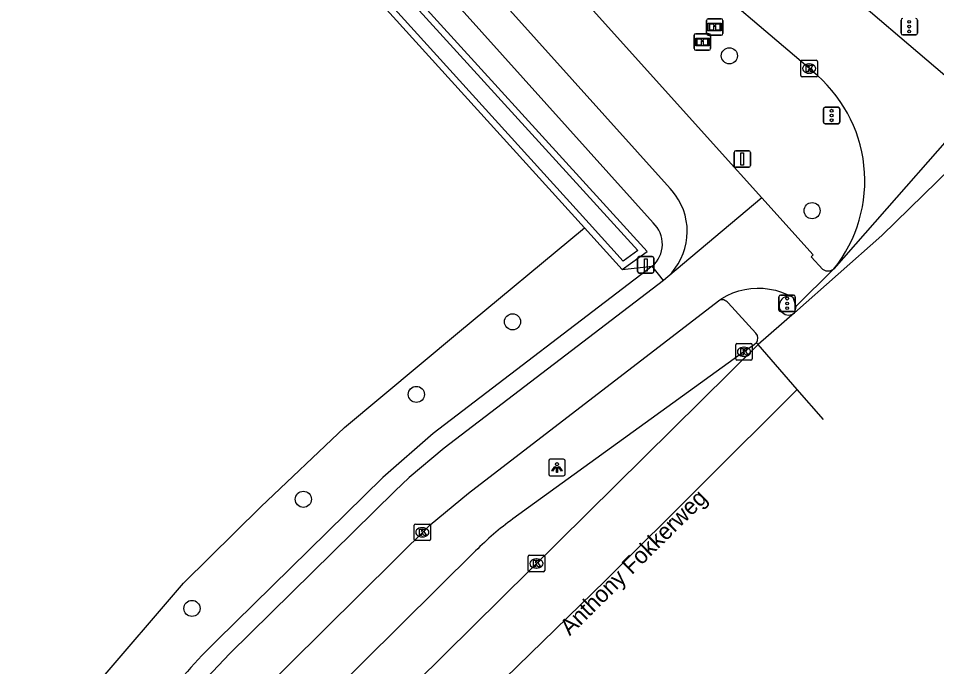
# Model space of a CAD drawing. Extents: x 157321 to 158827, y 386650 to 388532.
# Drawn here: x 158300.1 to 158355.8, y 386849.9 to 386889.2 of the extents above; entities that cross this region are included whole.
import ezdxf

# ---------------------------------------------------------------- set-up
doc = ezdxf.new("R2010")
doc.units = 0
for name, color, linetype in [('IMGEO_Boom', 7, 'Continuous'), ('IMGEO_Bouwland', 7, 'Continuous'), ('IMGEO_Fietspad_gesloten', 7, 'Continuous'), ('IMGEO_Grasland_overig', 7, 'Continuous'), ('IMGEO_Groenvoorziening', 7, 'Continuous'), ('IMGEO_Informatiebord', 7, 'Continuous'), ('IMGEO_Kolk', 7, 'Continuous'), ('IMGEO_Lichtpunt', 7, 'Continuous'), ('IMGEO_Openbare_ruimte_label', 7, 'Continuous'), ('IMGEO_OVBaan_open', 7, 'Continuous'), ('IMGEO_Rijbaan_lokaal_gesloten', 7, 'Continuous'), ('IMGEO_Rijbaan_regionaal_gesloten', 7, 'Continuous'), ('IMGEO_Verkeersbordpaal', 7, 'Continuous'), ('IMGEO_Verkeersregelinstallatiepaal', 7, 'Continuous'), ('IMGEO_Voetpad_open', 7, 'Continuous'), ('IMGEO_Waterloop', 7, 'Continuous')]:
    doc.layers.add(name, color=color, linetype=linetype)

msp = doc.modelspace()

# ---------------------------------------------------------------- linework, layer by layer
at = {"layer": 'IMGEO_Boom'}
for centre in [(158343.218, 386886.885), (158348.234, 386877.495), (158330.072, 386870.76), (158324.239, 386866.357), (158317.388, 386859.998), (158310.633, 386853.383)]:
    msp.add_circle(centre, 0.489, dxfattribs=at)
at = {"layer": 'IMGEO_Bouwland'}
msp.add_lwpolyline([(158334.432, 386876.454), (158305.326, 386908.574)], dxfattribs=at)
at = {"layer": 'IMGEO_Fietspad_gesloten'}
for points in [[(158309.295, 386916.737), (158310.55, 386915.72), (158312.938, 386913.791), (158314.825, 386912.014), (158342.42, 386881.352), (158345.182, 386878.283)], [(158339.487, 386873.493), (158339.722, 386873.737), (158339.934, 386874.001), (158340.121, 386874.282), (158340.282, 386874.58), (158340.417, 386874.89), (158340.523, 386875.211), (158340.599, 386875.541), (158340.646, 386875.876), (158340.663, 386876.214), (158340.65, 386876.552), (158340.607, 386876.887), (158340.534, 386877.217), (158340.431, 386877.54), (158340.3, 386877.852), (158340.142, 386878.151), (158339.958, 386878.435), (158339.749, 386878.701), (158339.626, 386878.837), (158311.543, 386910.095)], [(158345.182, 386878.283), (158339.487, 386873.493)], [(158349.552, 386873.965), (158349.544, 386873.958), (158349.511, 386873.928), (158349.475, 386873.902), (158349.437, 386873.88), (158349.397, 386873.86), (158349.355, 386873.845), (158349.313, 386873.833), (158349.269, 386873.825), (158349.225, 386873.821), (158349.18, 386873.821), (158349.136, 386873.825), (158349.092, 386873.833), (158349.05, 386873.845), (158349.008, 386873.86), (158348.968, 386873.879), (158348.93, 386873.902), (158348.894, 386873.928), (158348.171, 386874.69), (158348.294, 386874.825), (158345.182, 386878.283)], [(158339.487, 386873.493), (158339.232, 386873.271)], [(158339.232, 386873.271), (158325.932, 386863.096), (158323.808, 386861.322), (158322.942, 386860.499), (158312.939, 386850.645), (158310.821, 386848.424)], [(158342.559, 386872.036), (158342.758, 386872.167), (158343.086, 386872.351), (158343.43, 386872.505), (158343.786, 386872.627), (158344.151, 386872.717), (158344.523, 386872.774), (158344.899, 386872.798), (158345.275, 386872.788), (158345.649, 386872.744), (158346.018, 386872.667), (158346.378, 386872.558), (158346.727, 386872.417), (158347.062, 386872.245)], [(158312.86, 386846.165), (158313.045, 386846.383), (158314.4, 386847.876), (158325.081, 386858.443), (158327.393, 386860.364), (158342.559, 386872.036)], [(158347.062, 386872.245), (158347.257, 386871.677)]]:
    msp.add_lwpolyline(points, dxfattribs=at)
at = {"layer": 'IMGEO_Grasland_overig'}
for points in [[(158235.862, 386778.219), (158242.426, 386783.422), (158246.347, 386786.767), (158250.859, 386790.582), (158258.201, 386797.764), (158265.423, 386804.471), (158271.234, 386810.341), (158276.426, 386815.611), (158281.179, 386820.446), (158289.869, 386831.241), (158304.891, 386848.81), (158310.122, 386854.921), (158314.804, 386859.543), (158319.874, 386864.355), (158326.724, 386870.062), (158334.432, 386876.454)], [(158334.432, 386876.454), (158336.725, 386873.923)], [(158336.725, 386873.923), (158338.546, 386874.13)]]:
    msp.add_lwpolyline(points, dxfattribs=at)
at = {"layer": 'IMGEO_Groenvoorziening'}
msp.add_lwpolyline([(158336.725, 386873.923), (158338.242, 386875.02), (158304.966, 386911.573), (158303.723, 386910.343)], dxfattribs=at)
at = {"layer": 'IMGEO_Informatiebord'}
for p, q in [((158341.839, 386888.229), (158341.839, 386889.029)), ((158341.839, 386889.029), (158341.839, 386888.229)), ((158341.939, 386889.129), (158342.729, 386889.129)), ((158342.729, 386889.129), (158341.939, 386889.129)), ((158342.829, 386889.029), (158342.829, 386888.229)), ((158342.829, 386888.229), (158342.829, 386889.029)), ((158341.083, 386887.326), (158341.083, 386888.126)), ((158341.083, 386888.126), (158341.083, 386887.326)), ((158341.183, 386888.226), (158341.973, 386888.226)), ((158341.973, 386888.226), (158341.183, 386888.226)), ((158342.729, 386888.129), (158341.939, 386888.129)), ((158341.939, 386888.129), (158342.729, 386888.129)), ((158342.073, 386888.126), (158342.073, 386887.326)), ((158342.073, 386887.326), (158342.073, 386888.126)), ((158341.973, 386887.226), (158341.183, 386887.226)), ((158341.183, 386887.226), (158341.973, 386887.226))]:
    msp.add_line(p, q, dxfattribs=at)
for points in [[(158341.94, 386888.861), (158342.728, 386888.861), (158342.728, 386888.397), (158341.94, 386888.397), (158341.94, 386888.861)], [(158342.005, 386888.796), (158342.005, 386888.462), (158342.28, 386888.462), (158342.281, 386888.675), (158342.385, 386888.676), (158342.386, 386888.462), (158342.663, 386888.462), (158342.663, 386888.796), (158342.387, 386888.796), (158342.387, 386888.716), (158342.281, 386888.716), (158342.281, 386888.796), (158342.005, 386888.796)], [(158341.184, 386887.958), (158341.972, 386887.958), (158341.972, 386887.494), (158341.184, 386887.494), (158341.184, 386887.958)], [(158341.249, 386887.893), (158341.249, 386887.559), (158341.524, 386887.559), (158341.525, 386887.772), (158341.629, 386887.773), (158341.63, 386887.559), (158341.907, 386887.559), (158341.907, 386887.893), (158341.631, 386887.893), (158341.631, 386887.813), (158341.525, 386887.813), (158341.525, 386887.893), (158341.249, 386887.893)]]:
    msp.add_lwpolyline(points, dxfattribs=at)
for centre, start, end in [((158341.939, 386889.029), 90, 180), ((158341.939, 386889.029), 90, 180), ((158342.729, 386889.029), 0, 90), ((158342.729, 386889.029), 360, 90), ((158341.183, 386888.126), 90, 180), ((158341.183, 386888.126), 90, 180), ((158341.939, 386888.229), 180, 270), ((158341.939, 386888.229), 180, 270), ((158341.973, 386888.126), 0, 90), ((158341.973, 386888.126), 360, 90), ((158342.729, 386888.229), 270, 0), ((158342.729, 386888.229), 270, 0), ((158341.183, 386887.326), 180, 270), ((158341.183, 386887.326), 180, 270), ((158341.973, 386887.326), 270, 0), ((158341.973, 386887.326), 270, 0)]:
    msp.add_arc(centre, 0.1, start, end, dxfattribs=at)
at = {"layer": 'IMGEO_Kolk'}
for p, q in [((158347.557, 386885.684), (158347.557, 386886.536)), ((158347.632, 386886.61), (158348.484, 386886.61)), ((158348.045, 386886.39), (158348.07, 386886.39)), ((158348.558, 386886.536), (158348.558, 386885.684)), ((158348.068, 386885.83), (158348.043, 386885.83)), ((158348.484, 386885.61), (158347.632, 386885.61)), ((158343.602, 386868.509), (158343.602, 386869.361)), ((158343.677, 386869.435), (158344.529, 386869.435)), ((158344.09, 386869.215), (158344.115, 386869.215)), ((158344.603, 386869.361), (158344.603, 386868.509)), ((158344.529, 386868.435), (158343.677, 386868.435)), ((158344.113, 386868.655), (158344.088, 386868.655)), ((158324.102, 386857.57), (158324.102, 386858.422)), ((158324.177, 386858.496), (158325.029, 386858.496)), ((158325.103, 386858.422), (158325.103, 386857.57)), ((158324.59, 386858.276), (158324.615, 386858.276)), ((158325.029, 386857.496), (158324.177, 386857.496)), ((158324.613, 386857.716), (158324.588, 386857.716)), ((158331.018, 386855.678), (158331.018, 386856.53)), ((158331.093, 386856.604), (158331.945, 386856.604)), ((158331.506, 386856.384), (158331.531, 386856.384)), ((158332.019, 386856.53), (158332.019, 386855.678)), ((158331.945, 386855.604), (158331.093, 386855.604)), ((158331.529, 386855.824), (158331.504, 386855.824))]:
    msp.add_line(p, q, dxfattribs=at)
for points in [[(158347.557, 386885.684), (158347.557, 386886.536)], [(158347.632, 386886.61), (158348.484, 386886.61)], [(158347.878, 386886.31), (158348.001, 386886.31), (158348.001, 386886.159), (158348.131, 386886.31), (158348.295, 386886.31), (158348.149, 386886.159), (158348.302, 386885.91), (158348.15, 386885.91), (158348.065, 386886.074), (158348.001, 386886.007), (158348.001, 386885.91), (158347.878, 386885.91), (158347.878, 386886.31)], [(158348.558, 386886.536), (158348.558, 386885.684)], [(158348.484, 386885.61), (158347.632, 386885.61)], [(158343.602, 386868.509), (158343.602, 386869.361)], [(158343.677, 386869.435), (158344.529, 386869.435)], [(158343.923, 386869.135), (158344.046, 386869.135), (158344.046, 386868.984), (158344.176, 386869.135), (158344.34, 386869.135), (158344.194, 386868.984), (158344.347, 386868.735), (158344.195, 386868.735), (158344.11, 386868.899), (158344.046, 386868.832), (158344.046, 386868.735), (158343.923, 386868.735), (158343.923, 386869.135)], [(158344.603, 386869.361), (158344.603, 386868.509)], [(158344.529, 386868.435), (158343.677, 386868.435)], [(158324.102, 386857.57), (158324.102, 386858.422)], [(158324.177, 386858.496), (158325.029, 386858.496)], [(158325.103, 386858.422), (158325.103, 386857.57)], [(158324.423, 386858.196), (158324.546, 386858.196), (158324.546, 386858.045), (158324.676, 386858.196), (158324.84, 386858.196), (158324.694, 386858.045), (158324.847, 386857.796), (158324.695, 386857.796), (158324.61, 386857.96), (158324.546, 386857.893), (158324.546, 386857.796), (158324.423, 386857.796), (158324.423, 386858.196)], [(158325.029, 386857.496), (158324.177, 386857.496)], [(158331.018, 386855.678), (158331.018, 386856.53)], [(158331.093, 386856.604), (158331.945, 386856.604)], [(158331.339, 386856.304), (158331.462, 386856.304), (158331.462, 386856.153), (158331.592, 386856.304), (158331.756, 386856.304), (158331.61, 386856.153), (158331.763, 386855.904), (158331.611, 386855.904), (158331.526, 386856.068), (158331.462, 386856.001), (158331.462, 386855.904), (158331.339, 386855.904), (158331.339, 386856.304)], [(158332.019, 386856.53), (158332.019, 386855.678)], [(158331.945, 386855.604), (158331.093, 386855.604)]]:
    msp.add_lwpolyline(points, dxfattribs=at)
for centre, start, end in [((158347.634, 386886.534), 91.552, 178.448), ((158347.634, 386886.534), 91.552, 178.448), ((158348.482, 386886.534), 1.552, 88.448), ((158348.482, 386886.534), 1.552, 88.448), ((158347.634, 386885.686), 181.552, 268.448), ((158347.634, 386885.686), 181.552, 268.448), ((158348.482, 386885.686), 271.552, 358.448), ((158348.482, 386885.686), 271.552, 358.448), ((158343.679, 386869.359), 91.552, 178.448), ((158343.679, 386869.359), 91.552, 178.448), ((158344.527, 386869.359), 1.552, 88.448), ((158344.527, 386869.359), 1.552, 88.448), ((158343.679, 386868.511), 181.552, 268.448), ((158343.679, 386868.511), 181.552, 268.448), ((158344.527, 386868.511), 271.552, 358.448), ((158344.527, 386868.511), 271.552, 358.448), ((158324.179, 386858.42), 91.552, 178.448), ((158324.179, 386858.42), 91.552, 178.448), ((158325.027, 386858.42), 1.552, 88.448), ((158325.027, 386858.42), 1.552, 88.448), ((158324.179, 386857.572), 181.552, 268.448), ((158324.179, 386857.572), 181.552, 268.448), ((158325.027, 386857.572), 271.552, 358.448), ((158325.027, 386857.572), 271.552, 358.448), ((158331.095, 386856.528), 91.552, 178.448), ((158331.095, 386856.528), 91.552, 178.448), ((158331.943, 386856.528), 1.552, 88.448), ((158331.943, 386856.528), 1.552, 88.448), ((158331.095, 386855.68), 181.552, 268.448), ((158331.095, 386855.68), 181.552, 268.448), ((158331.943, 386855.68), 271.552, 358.448), ((158331.943, 386855.68), 271.552, 358.448)]:
    msp.add_arc(centre, 0.0765, start, end, dxfattribs=at)
for centre, major_axis, ratio, start_param, end_param in [((158348.044, 386886.11), (-0.387, 0.002), 0.722429, 4.712389, 7.853982), ((158348.069, 386886.11), (-0.39, 0.002), 0.717154, 1.570796, 4.712389), ((158344.089, 386868.935), (-0.387, 0.002), 0.722429, 4.712389, 7.853982), ((158344.114, 386868.935), (-0.39, 0.002), 0.717154, 1.570796, 4.712389), ((158324.589, 386857.996), (-0.387, 0.002), 0.722429, 4.712389, 7.853982), ((158324.614, 386857.996), (-0.39, 0.002), 0.717154, 1.570796, 4.712389), ((158331.505, 386856.104), (-0.387, 0.002), 0.722429, 4.712389, 7.853982), ((158331.53, 386856.104), (-0.39, 0.002), 0.717154, 1.570796, 4.712389)]:
    msp.add_ellipse(centre, major_axis=major_axis, ratio=ratio, start_param=start_param, end_param=end_param, dxfattribs=at)
at = {"layer": 'IMGEO_Lichtpunt'}
for p, q in [((158332.268, 386862.33), (158332.268, 386861.523)), ((158332.268, 386862.33), (158332.268, 386861.523)), ((158333.17, 386862.425), (158332.362, 386862.425)), ((158333.17, 386862.425), (158332.362, 386862.425)), ((158333.264, 386861.523), (158333.264, 386862.33)), ((158333.264, 386861.523), (158333.264, 386862.33)), ((158332.362, 386861.429), (158333.17, 386861.429)), ((158332.362, 386861.429), (158333.17, 386861.429))]:
    msp.add_line(p, q, dxfattribs=at)
for points in [[(158332.642, 386861.994), (158332.681, 386861.966), (158332.493, 386861.704), (158332.455, 386861.731), (158332.642, 386861.994)], [(158332.744, 386861.946), (158332.791, 386861.946), (158332.791, 386861.624), (158332.744, 386861.624), (158332.744, 386861.946)], [(158332.854, 386861.966), (158332.892, 386861.993), (158333.079, 386861.731), (158333.04, 386861.703), (158332.854, 386861.966)]]:
    msp.add_lwpolyline(points, dxfattribs=at)
msp.add_circle((158332.767, 386862.128), 0.0994, dxfattribs=at)
for centre, start, end in [((158332.362, 386862.33), 90, 180), ((158332.362, 386862.33), 90, 180), ((158333.17, 386862.33), 0, 90), ((158333.17, 386862.33), 0, 90), ((158332.362, 386861.523), 180, 270), ((158332.362, 386861.523), 180, 270), ((158333.17, 386861.523), 270, 0), ((158333.17, 386861.523), 270, 360)]:
    msp.add_arc(centre, 0.0946, start, end, dxfattribs=at)
at = {"layer": 'IMGEO_OVBaan_open'}
for points in [[(158344.858, 386869.486), (158344.727, 386869.364), (158344.104, 386868.934), (158330.087, 386858.806)], [(158344.967, 386869.389), (158344.858, 386869.486)], [(158344.967, 386869.389), (158293.079, 386818.127)], [(158327.83, 386856.869), (158316.458, 386845.62), (158315.041, 386844.17)]]:
    msp.add_lwpolyline(points, dxfattribs=at)
msp.add_arc((158341.795, 386842.881), 19.766, 126.322, 134.9517, dxfattribs=at)
at = {"layer": 'IMGEO_Rijbaan_lokaal_gesloten'}
for points in [[(158348.232, 386885.963), (158332.438, 386899.417), (158311.264, 386917.412), (158310.489, 386918.059)], [(158333.477, 386905.159), (158356.83, 386885.245)]]:
    msp.add_lwpolyline(points, dxfattribs=at)
msp.add_arc((158342.904, 386879.305), 8.527, 321.2268, 51.3299, dxfattribs=at)
at = {"layer": 'IMGEO_Rijbaan_regionaal_gesloten'}
for points in [[(158376.822, 386899.78), (158352.454, 386875.994), (158347.176, 386871.304)], [(158359.631, 386885.438), (158349.552, 386873.965)], [(158347.257, 386871.677), (158349.552, 386873.965)], [(158347.176, 386871.304), (158344.967, 386869.389)], [(158347.257, 386871.677), (158347.176, 386871.304)], [(158347.338, 386866.652), (158344.967, 386869.389)], [(158130.556, 386652.21), (158151.056, 386672.76), (158161.945, 386683.393), (158181.844, 386703.082), (158200.321, 386721.363), (158241.47, 386762.076), (158261.924, 386782.315), (158286.694, 386806.822), (158320.475, 386840.246), (158335.714, 386855.078), (158347.338, 386866.652)], [(158348.917, 386864.83), (158347.338, 386866.652)]]:
    msp.add_lwpolyline(points, dxfattribs=at)
at = {"layer": 'IMGEO_Verkeersbordpaal'}
for p, q in [((158343.503, 386880.232), (158343.503, 386881.032)), ((158343.503, 386881.032), (158343.503, 386880.232)), ((158343.603, 386881.132), (158344.393, 386881.132)), ((158344.393, 386881.132), (158343.603, 386881.132)), ((158344.493, 386881.032), (158344.493, 386880.232)), ((158344.493, 386880.232), (158344.493, 386881.032)), ((158344.393, 386880.132), (158343.603, 386880.132)), ((158343.603, 386880.132), (158344.393, 386880.132)), ((158337.654, 386873.808), (158337.654, 386874.608)), ((158337.654, 386874.608), (158337.654, 386873.808)), ((158337.754, 386874.708), (158338.544, 386874.708)), ((158338.544, 386874.708), (158337.754, 386874.708)), ((158338.644, 386874.608), (158338.644, 386873.808)), ((158338.644, 386873.808), (158338.644, 386874.608)), ((158338.544, 386873.708), (158337.754, 386873.708)), ((158337.754, 386873.708), (158338.544, 386873.708))]:
    msp.add_line(p, q, dxfattribs=at)
for points in [[(158343.923, 386881.007), (158344.073, 386881.007), (158344.073, 386880.257), (158343.923, 386880.257), (158343.923, 386881.007)], [(158338.074, 386874.583), (158338.224, 386874.583), (158338.224, 386873.833), (158338.074, 386873.833), (158338.074, 386874.583)]]:
    msp.add_lwpolyline(points, dxfattribs=at)
for centre, start, end in [((158343.603, 386881.032), 90, 180), ((158343.603, 386881.032), 90, 180), ((158344.393, 386881.032), 0, 90), ((158344.393, 386881.032), 360, 90), ((158343.603, 386880.232), 180, 270), ((158343.603, 386880.232), 180, 270), ((158344.393, 386880.232), 270, 0), ((158344.393, 386880.232), 270, 0), ((158337.754, 386874.608), 90, 180), ((158337.754, 386874.608), 90, 180), ((158338.544, 386874.608), 0, 90), ((158338.544, 386874.608), 360, 90), ((158337.754, 386873.808), 180, 270), ((158337.754, 386873.808), 180, 270), ((158338.544, 386873.808), 270, 0), ((158338.544, 386873.808), 270, 0)]:
    msp.add_arc(centre, 0.1, start, end, dxfattribs=at)
at = {"layer": 'IMGEO_Verkeersregelinstallatiepaal'}
for p, q in [((158353.63, 386888.254), (158353.63, 386889.054)), ((158353.63, 386889.054), (158353.63, 386888.254)), ((158354.62, 386889.054), (158354.62, 386888.254)), ((158354.62, 386888.254), (158354.62, 386889.054)), ((158354.52, 386888.154), (158353.73, 386888.154)), ((158353.73, 386888.154), (158354.52, 386888.154)), ((158348.924, 386882.865), (158348.924, 386883.665)), ((158348.924, 386883.665), (158348.924, 386882.865)), ((158349.024, 386883.765), (158349.814, 386883.765)), ((158349.814, 386883.765), (158349.024, 386883.765)), ((158349.914, 386883.665), (158349.914, 386882.865)), ((158349.914, 386882.865), (158349.914, 386883.665)), ((158349.814, 386882.765), (158349.024, 386882.765)), ((158349.024, 386882.765), (158349.814, 386882.765)), ((158346.226, 386871.473), (158346.226, 386872.273)), ((158346.226, 386872.273), (158346.226, 386871.473)), ((158346.326, 386872.373), (158347.116, 386872.373)), ((158347.116, 386872.373), (158346.326, 386872.373)), ((158347.216, 386872.273), (158347.216, 386871.473)), ((158347.216, 386871.473), (158347.216, 386872.273)), ((158347.116, 386871.373), (158346.326, 386871.373)), ((158346.326, 386871.373), (158347.116, 386871.373))]:
    msp.add_line(p, q, dxfattribs=at)
for centre in [(158354.125, 386888.944), (158354.125, 386888.654), (158354.125, 386888.364), (158349.419, 386883.555), (158349.419, 386883.265), (158349.419, 386882.975), (158346.721, 386872.163), (158346.721, 386871.873), (158346.721, 386871.583)]:
    msp.add_circle(centre, 0.085, dxfattribs=at)
for centre, start, end in [((158353.73, 386889.054), 90, 180), ((158353.73, 386889.054), 90, 180), ((158354.52, 386889.054), 0, 90), ((158354.52, 386889.054), 360, 90), ((158353.73, 386888.254), 180, 270), ((158353.73, 386888.254), 180, 270), ((158354.52, 386888.254), 270, 0), ((158354.52, 386888.254), 270, 0), ((158349.024, 386883.665), 90, 180), ((158349.024, 386883.665), 90, 180), ((158349.814, 386883.665), 0, 90), ((158349.814, 386883.665), 360, 90), ((158349.024, 386882.865), 180, 270), ((158349.024, 386882.865), 180, 270), ((158349.814, 386882.865), 270, 0), ((158349.814, 386882.865), 270, 0), ((158346.326, 386872.273), 90, 180), ((158346.326, 386872.273), 90, 180), ((158347.116, 386872.273), 0, 90), ((158347.116, 386872.273), 360, 90), ((158346.326, 386871.473), 180, 270), ((158346.326, 386871.473), 180, 270), ((158347.116, 386871.473), 270, 0), ((158347.116, 386871.473), 270, 0)]:
    msp.add_arc(centre, 0.1, start, end, dxfattribs=at)
at = {"layer": 'IMGEO_Voetpad_open'}
for points in [[(158309.94, 386908.663), (158338.595, 386876.75)], [(158338.546, 386874.13), (158325.261, 386863.991), (158322.198, 386861.316), (158312.146, 386851.446)], [(158339.232, 386873.271), (158338.546, 386874.13)], [(158344.832, 386870.062), (158343.139, 386871.902)]]:
    msp.add_lwpolyline(points, dxfattribs=at)
for centre, radius, start, end in [((158337.395, 386875.462), 1.761, 310.8372, 47.0199), ((158346.809, 386871.737), 0.568, 63.4999, 310.3153), ((158342.774, 386871.646), 0.446, 35.0745, 118.9074), ((158344.485, 386869.758), 0.462, 323.9264, 41.2426), ((158338.857, 386824.253), 38.118, 134.4883, 142.285)]:
    msp.add_arc(centre, radius, start, end, dxfattribs=at)
at = {"layer": 'IMGEO_Waterloop'}
msp.add_lwpolyline([(158304.952, 386911.018), (158337.668, 386875.079), (158336.779, 386874.436), (158334.717, 386876.712), (158304.255, 386910.329), (158304.952, 386911.018)], dxfattribs=at)

# ---------------------------------------------------------------- texts
at = {"layer": 'IMGEO_Openbare_ruimte_label'}
msp.add_text('Anthony Fokkerweg', height=1, rotation=44.6356, dxfattribs=at).set_placement((158333.54, 386851.683))

doc.saveas('drawing.dxf')
